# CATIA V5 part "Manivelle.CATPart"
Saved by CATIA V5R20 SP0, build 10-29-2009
Part number: Manivelle
Bounding box of the stored display mesh (mm): x -20 to 20, y -55 to 55, z -15 to 15
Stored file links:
  C:\Users\Anne\Documents\IFMA\2e année\3e semestre\IAO\Projet\Catia\Manivelle.CATPart
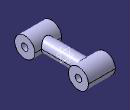
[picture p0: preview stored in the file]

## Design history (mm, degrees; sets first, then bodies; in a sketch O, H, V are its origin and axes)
Parameters
  `Longueur L` = 80 mm
  D_Trou = 10 mm
  D_Pivot = 30 mm
  D_Bielle = 20 mm
  `Largeur La` = 40 mm
Body1 (main body)
  Sketch1 on yz-plane, origin (0, 0, 0), H (0, 1, 0), V (0, 0, 1)
    circle A1 centre (40, 0) radius 15
    point P1 (40, 0)
    point P2 (-40, 0)
    circle A2 centre (-40, 0) radius 15
    radius A1 = 15 {= D_Pivot  /2}
    distance P2 P1 = 80 {= `Longueur L`}
    coincidence: P1 H
    symmetry: A1 A2 V
  Pad1: profile Sketch1, direction (1, 0, 0), length 20 {= `Largeur La` /2}, mirrored extent
  Sketch2 on zx-plane, origin (0, 0, 0), H (-1, 0, 0), V (0, 0, 1)
    circle A1 centre (0, 0) radius 10
    point P1 (10, 0)
    radius A1 = 10 {= D_Bielle /2}
    coincidence: P1 A1, P1 H
  Pad2: profile Sketch2, direction (0, 1, 0), length 40 {= `Longueur L` /2}, mirrored extent
  Sketch3 on end face of Pad1, origin (20, 96.2753, 0), H (0, 1, 0), V (0, 0, 1)
    point P1 (-56.2753, 0)
    reference projected circle E1 centre (-56.2753, 0) radius 15 from edge [face of Pad1 from Sketch1.A1 | end face of Pad1]
    concentricity: P1 E1
  Hole1: placed by Sketch3, at (20, 40, 0) direction (-1, 0, 0), diameter 10 {= D_Trou}, through (limit type 6)
  RectPattern1: of Hole1, direction 1 instances 2, spacing 80 {= `Longueur L`}, along axis of face of Pad2 from Sketch2.A1 reversed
